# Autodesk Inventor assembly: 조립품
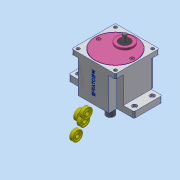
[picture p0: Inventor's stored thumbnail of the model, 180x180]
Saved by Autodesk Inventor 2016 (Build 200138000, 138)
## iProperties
Created: 2020-08
Part Number: 조립품
Material: 일반
Document SubType Name: Assembly
Designer: User
Author: User
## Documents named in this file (10)
- C:\Users\User\Desktop\700815V1006\조립품.iam
- C:\Users\User\Desktop\700815V1006\메인 축.ipt
- C:\Users\User\Desktop\700815V1006\베어링 608.ipt
- C:\Users\User\Desktop\700815V1006\베어링 6003.ipt
- C:\Users\User\Desktop\700815V1006\본체.ipt
- C:\Users\User\Desktop\700815V1006\볼트 M4.ipt
- C:\Users\User\Desktop\700815V1006\서브 축.ipt
- C:\Users\User\Desktop\700815V1006\오일 실 8 22 7.ipt
- C:\Users\User\Desktop\700815V1006\오일 실 17 32 8.ipt
- C:\Users\User\Desktop\700815V1006\커버.ipt
